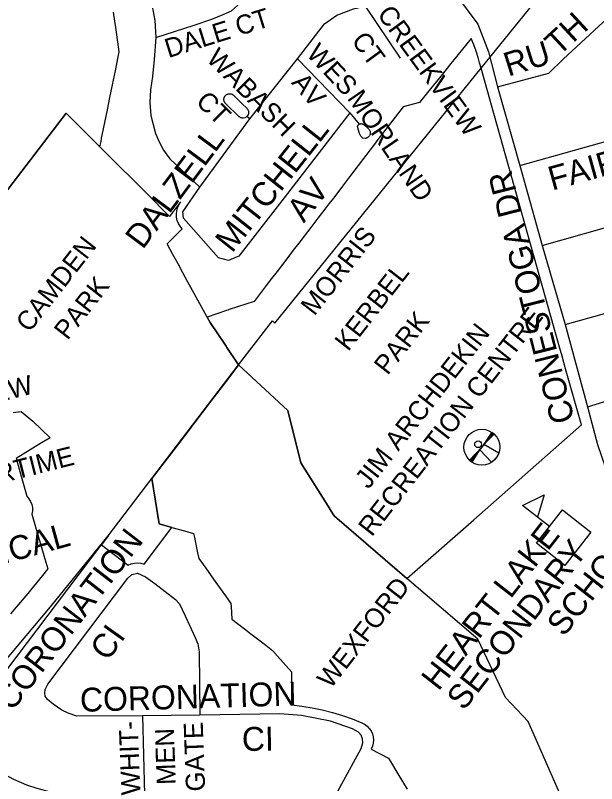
# Model space of a CAD drawing. Extents: x 586326 to 623965, y 4819854 to 4857850.
# Drawn here: x 597005 to 597614, y 4840854 to 4841658 of the extents above; entities that cross this region are included whole.
import ezdxf

# ---------------------------------------------------------------- set-up
doc = ezdxf.new("R2010")
doc.units = 0
for name, color, linetype in [('Lots_Concessions', 7, 'Continuous'), ('Minor Rd Lbls', 7, 'Continuous'), ('Minor Rds', 7, 'Continuous'), ('Park Lbls', 7, 'Continuous'), ('Park Outlines', 7, 'Continuous'), ('Proposed Secondary Rds', 7, 'Continuous'), ('Rec Lbls', 7, 'Continuous'), ('Rec Syms', 7, 'Continuous'), ('School Syms_Lbls', 7, 'Continuous'), ('Secondary Rds Lbls', 7, 'Continuous')]:
    doc.layers.add(name, color=color, linetype=linetype)

msp = doc.modelspace()

# ---------------------------------------------------------------- linework, layer by layer
at = {"layer": 'Lots_Concessions'}
for p, q in [((597492.8, 4841602.45), (597648.92, 4841795.28)), ((597492.8, 4841602.45), (597566.85, 4841693.91)), ((597276.97, 4841335.87), (597492.8, 4841602.45)), ((597239.14, 4841292.03), (597274.52, 4841338.28)), ((597274.52, 4841338.28), (597276.97, 4841335.87)), ((597148.4, 4841173.28), (597239.14, 4841292.03)), ((597102.63, 4841113.22), (597148.4, 4841173.28)), ((596954.95, 4840918.59), (597102.63, 4841113.22))]:
    msp.add_line(p, q, dxfattribs=at)
at = {"layer": 'Minor Rds'}
for points in [[(597509.86, 4841583.05), (597563.65, 4841597.08), (597578.61, 4841611.85), (597699.29, 4841723.95)], [(597134.5, 4841711.67), (597143.12, 4841688.57), (597148.22, 4841669.1), (597151.41, 4841652.39), (597152.63, 4841634.5)], [(597152.63, 4841634.5), (597192.62, 4841647.32), (597211.05, 4841653.86), (597222.91, 4841658.48), (597231.69, 4841662.41), (597238.03, 4841668.08), (597254.63, 4841691.28)], [(597300.55, 4841612.28), (597328.91, 4841648.79), (597341.81, 4841657.98), (597359.46, 4841664.34), (597371.38, 4841667.4)], [(597371.38, 4841667.4), (597408.04, 4841612.75)], [(597152.63, 4841634.5), (597150.88, 4841611.41), (597148.93, 4841593.64), (597146.88, 4841579.82), (597146.12, 4841566.64), (597147.21, 4841553.09), (597149.54, 4841543.39), (597152.24, 4841534.18), (597155.87, 4841525.5), (597160.5, 4841516.8), (597167.2, 4841507.5), (597198.36, 4841477.83)], [(597250.84, 4841549.29), (597300.55, 4841612.28)], [(597300.55, 4841612.28), (597355.51, 4841555.57)], [(597247.86, 4841551.98), (597246.99, 4841551.25), (597245.75, 4841550.63), (597244.37, 4841550.3), (597243.19, 4841550.21), (597242.98, 4841550.23), (597242.78, 4841550.27), (597241.98, 4841550.44), (597241.78, 4841550.49), (597241.58, 4841550.55), (597241.39, 4841550.63), (597241.2, 4841550.72), (597240.49, 4841551.11), (597240.31, 4841551.21), (597240.13, 4841551.33), (597239.97, 4841551.45), (597239.82, 4841551.59), (597225.35, 4841565.53), (597225.18, 4841565.71), (597225.02, 4841565.9), (597224.88, 4841566.11), (597224.44, 4841566.81), (597224.34, 4841566.99), (597224.25, 4841567.17), (597224.18, 4841567.36), (597224.11, 4841567.55), (597223.88, 4841568.35), (597223.83, 4841568.55), (597223.79, 4841568.75), (597223.77, 4841568.95), (597223.76, 4841569.16), (597223.75, 4841569.99), (597223.75, 4841570.19), (597223.77, 4841570.39), (597223.8, 4841570.6), (597223.85, 4841570.8), (597224.06, 4841571.6), (597224.12, 4841571.79), (597224.2, 4841571.98), (597224.28, 4841572.17), (597224.38, 4841572.35), (597224.8, 4841573.06), (597224.91, 4841573.23), (597225.03, 4841573.4), (597225.16, 4841573.56), (597225.31, 4841573.7), (597225.74, 4841574.12)], [(597225.74, 4841574.12), (597226.06, 4841574.41), (597226.22, 4841574.54), (597226.39, 4841574.65), (597226.56, 4841574.76), (597227.3, 4841575.15), (597227.48, 4841575.24), (597227.67, 4841575.32), (597227.86, 4841575.38), (597228.06, 4841575.43), (597228.87, 4841575.61), (597229.07, 4841575.65), (597229.27, 4841575.67), (597229.48, 4841575.68), (597229.68, 4841575.68), (597230.51, 4841575.64), (597230.71, 4841575.62), (597230.91, 4841575.59), (597231.11, 4841575.54), (597231.31, 4841575.48), (597232.1, 4841575.22), (597232.34, 4841575.12), (597232.58, 4841575), (597232.81, 4841574.86), (597233.03, 4841574.71), (597233.23, 4841574.53), (597241.05, 4841566.94), (597242.9, 4841565.17), (597242.93, 4841565.13), (597247.64, 4841560.47), (597247.78, 4841560.32), (597248.32, 4841559.71), (597248.45, 4841559.55), (597248.57, 4841559.38), (597248.68, 4841559.2), (597248.77, 4841559.02), (597249.12, 4841558.28), (597249.21, 4841558.09), (597249.27, 4841557.9), (597249.33, 4841557.7), (597249.37, 4841557.49), (597249.5, 4841556.69), (597249.53, 4841556.48), (597249.54, 4841556.28), (597249.54, 4841556.07), (597249.53, 4841555.86), (597249.43, 4841555.05), (597249.4, 4841554.85), (597249.36, 4841554.64), (597249.3, 4841554.44), (597249.23, 4841554.25), (597248.92, 4841553.49), (597248.83, 4841553.3), (597248.73, 4841553.12), (597248.62, 4841552.95), (597248.5, 4841552.78), (597247.86, 4841551.98)], [(597355.51, 4841555.57), (597281.73, 4841460.47), (597239.41, 4841405.9), (597230.8, 4841402.16)], [(597355.51, 4841555.57), (597365.21, 4841543.79)], [(597198.36, 4841477.83), (597250.84, 4841549.29)], [(597250.84, 4841549.29), (597247.86, 4841551.98)], [(597365.21, 4841543.79), (597365.28, 4841543.83), (597365.49, 4841543.94), (597365.72, 4841544.04), (597365.95, 4841544.12), (597366.48, 4841544.27), (597366.71, 4841544.33), (597366.96, 4841544.37), (597367.2, 4841544.39), (597367.45, 4841544.39), (597367.7, 4841544.37), (597368.24, 4841544.3), (597368.48, 4841544.25), (597368.72, 4841544.19), (597368.95, 4841544.11), (597369.18, 4841544.01), (597369.39, 4841543.89), (597369.86, 4841543.62), (597370.03, 4841543.51), (597370.19, 4841543.39), (597370.34, 4841543.26), (597375, 4841539.02), (597375.18, 4841538.84), (597375.35, 4841538.64), (597375.86, 4841537.99), (597375.99, 4841537.81), (597376.1, 4841537.62), (597376.2, 4841537.43), (597376.29, 4841537.23), (597376.59, 4841536.46), (597376.66, 4841536.25), (597376.72, 4841536.04), (597376.76, 4841535.82), (597376.78, 4841535.61), (597376.85, 4841534.78), (597376.85, 4841534.56), (597376.85, 4841534.34), (597376.82, 4841534.12), (597376.79, 4841533.91), (597376.61, 4841533.1), (597376.55, 4841532.88), (597376.48, 4841532.68), (597376.4, 4841532.47), (597376.3, 4841532.28), (597375.9, 4841531.55), (597375.65, 4841531.18), (597375.34, 4841530.84), (597374.77, 4841530.3)], [(597533.24, 4841500.61), (597702.65, 4841548.1)], [(597374.77, 4841530.3), (597374.13, 4841529.83), (597373.43, 4841529.44), (597373.19, 4841529.33), (597372.95, 4841529.23), (597372.7, 4841529.16), (597371.92, 4841528.97), (597371.67, 4841528.92), (597371.41, 4841528.89), (597368.94, 4841529.38), (597367.05, 4841531.24), (597365.48, 4841534.01), (597364.54, 4841537.53), (597363.57, 4841541.41), (597364.36, 4841543.04), (597365.21, 4841543.79)], [(597556.63, 4841417), (597822.65, 4841492.42), (597849.55, 4841508.21), (597890.17, 4841542.42)], [(597230.8, 4841402.16), (597228.63, 4841401.22), (597218.11, 4841404.14), (597181.28, 4841445.65), (597180.69, 4841452.08), (597198.36, 4841477.83)], [(597580.71, 4841334.36), (597958.13, 4841439.54), (597965.77, 4841440.98), (597971.84, 4841441.45), (597980.27, 4841440.98), (597988.01, 4841439.74), (597996.75, 4841436.74), (598003.13, 4841433.54), (598007.86, 4841430.42), (598014.54, 4841424.79), (598038.29, 4841400.86), (598039.72, 4841398.11), (598040.09, 4841395.77), (598040.07, 4841392.52)], [(597604.23, 4841248.33), (597689.35, 4841274.34)], [(597138.46, 4840925.09), (597069.97, 4840924.78), (597060.68, 4840927.61), (597054.14, 4840930.9), (597045, 4840937.18), (597039.2, 4840941.94), (597036.8, 4840945.63), (597036.32, 4840949), (597036.73, 4840952.54), (597039.36, 4840958.11), (597123.3, 4841068.88), (597127.5, 4841072.92), (597133.27, 4841074.33), (597141.63, 4841070.42), (597151.44, 4841063.47), (597172.9, 4841046.68), (597177.26, 4841042.03), (597183, 4841029.56), (597193.67, 4841007.08), (597196.27, 4841000.22), (597197.77, 4840991.82), (597198.53, 4840925.55)], [(597198.53, 4840925.55), (597138.46, 4840925.09)], [(597334.97, 4840831.49), (597367.47, 4840890.88), (597368.97, 4840896.85), (597368.83, 4840901.03), (597367.28, 4840904.75), (597364.39, 4840908.04), (597358.16, 4840911.31), (597335.13, 4840919.32), (597304.91, 4840925.31), (597282.35, 4840926.95), (597198.53, 4840925.55)], [(597138.46, 4840925.09), (597140.79, 4840842.66)]]:
    msp.add_lwpolyline(points, dxfattribs=at)
at = {"layer": 'Park Outlines'}
for points in [[(596979.02, 4841451.97), (597058.5, 4841555.49), (597069.52, 4841544.53), (597080.53, 4841533.57), (597084.42, 4841529.7), (597086.98, 4841527.16), (597093.95, 4841520.22), (597095.11, 4841525.9), (597095.78, 4841529.17), (597096.45, 4841532.45), (597099.12, 4841545.57), (597101.79, 4841558.69), (597104.47, 4841571.8), (597107.14, 4841584.92), (597110.15, 4841599.68), (597113.16, 4841614.43), (597114.2, 4841619.53), (597112.69, 4841629.94), (597110.5, 4841645.06), (597109.54, 4841651.7), (597108.17, 4841661.12)], [(596949.11, 4840928.35), (597042.38, 4841038.85), (597102.63, 4841113.22), (597095.54, 4841103.91), (597123.66, 4841082.57), (597126.8, 4841083.91), (597130.12, 4841084.69), (597133.53, 4841084.9), (597136.93, 4841084.52), (597140.21, 4841083.57), (597169.38, 4841122.05), (597155.83, 4841125.78), (597148.4, 4841173.28), (597175.02, 4841208.22), (597210.1, 4841254.07), (597219.45, 4841266.29), (597228.8, 4841278.51), (597239.14, 4841292.03), (597237.55, 4841294.38), (597226.87, 4841310.24), (597225.9, 4841311.67), (597209.32, 4841336.3), (597206.11, 4841342.13), (597192.52, 4841366.83), (597185.7, 4841379.35), (597180.71, 4841388.5), (597175.73, 4841397.64), (597170.25, 4841407.71), (597164.31, 4841418.62), (597179.98, 4841434.26), (597180.19, 4841434.49), (597177.99, 4841437.08), (597176.23, 4841439.99), (597174.96, 4841443.14), (597174.2, 4841446.45), (597173.98, 4841449.84), (597174.29, 4841453.23), (597175.15, 4841456.52), (597176.51, 4841459.63), (597178.35, 4841462.49), (597166.86, 4841447.45), (597163.46, 4841450.86), (597158.18, 4841456.17), (597151.67, 4841462.71), (597145.16, 4841469.24), (597142.81, 4841471.6), (597138.64, 4841475.76), (597132.1, 4841482.26), (597125.57, 4841488.76), (597116.63, 4841497.65), (597105.83, 4841508.4), (597093.95, 4841520.22), (597086.98, 4841527.16), (597084.42, 4841529.7), (597080.53, 4841533.57), (597069.52, 4841544.53), (597058.5, 4841555.49), (596979.02, 4841451.97)], [(597576.23, 4840841.2), (597542.08, 4840919.08), (597518.43, 4840944.13), (597489.29, 4841005.11), (597415.28, 4841068.65), (597339.41, 4841133.77), (597337.75, 4841136.4), (597331.04, 4841147.06), (597304.35, 4841189.47), (597290.73, 4841244.26), (597239.14, 4841292.03), (597228.8, 4841278.51), (597219.45, 4841266.29), (597210.1, 4841254.07), (597175.02, 4841208.22), (597148.4, 4841173.28), (597155.83, 4841125.78), (597169.38, 4841122.05), (597182.36, 4841118.49), (597192, 4841115.84), (597192.87, 4841111.67), (597196.23, 4841095.43), (597197.42, 4841089.69), (597204.68, 4841079.46), (597215.41, 4841064.34), (597225.34, 4841050.35), (597230.93, 4841042.47), (597231.17, 4841039.25), (597232.14, 4841026.06), (597246.73, 4841014.83), (597251.87, 4841010.87), (597265.81, 4841000.14), (597274.48, 4840993.48), (597279.79, 4840987.5), (597294.4, 4840971.06), (597294.46, 4840936.39), (597305.28, 4840935.18), (597316.03, 4840933.48), (597326.7, 4840931.3), (597337.26, 4840928.64), (597347.69, 4840925.5), (597357.97, 4840921.89), (597368.07, 4840917.83), (597370.98, 4840916.29), (597373.59, 4840914.29), (597375.84, 4840911.89), (597377.67, 4840909.16), (597379.02, 4840906.16), (597379.87, 4840902.98), (597380.18, 4840899.71), (597379.95, 4840896.42), (597379.18, 4840893.22), (597377.91, 4840890.19), (597395.87, 4840880.82), (597407.91, 4840860.73), (597415.4, 4840848.23)], [(597003.22, 4841242.37), (597011.49, 4841243.16), (597023.88, 4841233.13), (597041.81, 4841215.91), (597031.1, 4841209.39), (597013.73, 4841198.84), (597006.17, 4841194.24), (597017.52, 4841154.7), (597019.72, 4841152.13), (597021.45, 4841149.22), (597022.66, 4841146.06), (597023.31, 4841142.74), (597023.39, 4841139.36), (597022.89, 4841136.01), (597035.33, 4841092.77), (597039.37, 4841078.7), (597039.14, 4841078.42), (597033.83, 4841071.85), (597021.26, 4841056.34), (597018.46, 4841053.01), (597000.38, 4841031.6)]]:
    msp.add_lwpolyline(points, dxfattribs=at)
msp.add_lwpolyline([(597255.36, 4841358.53), (597229.27, 4841349.84), (597227.79, 4841349.35), (597226.32, 4841348.86), (597206.11, 4841342.13), (597209.32, 4841336.3), (597225.9, 4841311.67), (597226.87, 4841310.24), (597237.55, 4841294.38), (597239.14, 4841292.03), (597290.73, 4841244.26), (597304.35, 4841189.47), (597331.04, 4841147.06), (597337.75, 4841136.4), (597339.41, 4841133.77), (597415.28, 4841068.65), (597485.17, 4841130.12), (597597.81, 4841229.31), (597581.28, 4841288.05), (597577.63, 4841301.04), (597574.92, 4841310.66), (597503.7, 4841563.75), (597492.8, 4841602.46), (597491.28, 4841607.88), (597489.67, 4841613.58), (597487.61, 4841620.31), (597485.23, 4841626.94), (597482.54, 4841633.45), (597459.89, 4841605.48), (597452.28, 4841596.08), (597436.91, 4841577.1), (597428.22, 4841566.37), (597411.13, 4841562.15), (597384.91, 4841527.74), (597381.2, 4841522.87), (597355.21, 4841488.77), (597347.82, 4841479.07), (597338.56, 4841466.92), (597333.31, 4841460.03), (597329.29, 4841454.8), (597322.12, 4841445.46), (597314.69, 4841435.78), (597307.69, 4841426.67), (597302.02, 4841419.28), (597296.35, 4841411.9), (597290.67, 4841404.51), (597285, 4841397.12), (597279.32, 4841389.73), (597273.65, 4841382.34), (597267.98, 4841374.96)], close=True, dxfattribs=at)
at = {"layer": 'Proposed Secondary Rds'}
for points in [[(597466.01, 4841680.1), (597489.24, 4841648.52), (597500.74, 4841619.39), (597509.86, 4841583.05)], [(597509.86, 4841583.05), (597533.24, 4841500.61)], [(597533.24, 4841500.61), (597556.63, 4841417)], [(597556.63, 4841417), (597580.71, 4841334.36)], [(597580.71, 4841334.36), (597604.23, 4841248.33)], [(597604.23, 4841248.33), (597614.72, 4841208.96), (597622.7, 4841185.48), (597633.22, 4841165.6), (597652.57, 4841142.9), (597679.2, 4841116.07), (597912.93, 4840907.64)], [(597067.18, 4840841.17), (597055.25, 4840842.95), (597041.13, 4840845.46), (597028.32, 4840849.11), (597017.51, 4840852.33), (597003.86, 4840858.45), (596995.5, 4840863.09), (596983.85, 4840870.6)]]:
    msp.add_lwpolyline(points, dxfattribs=at)
at = {"layer": 'Rec Syms'}
for p, q in [((597505.15, 4841220.74), (597482.08, 4841191.22)), ((597482.08, 4841191.22), (597491.38, 4841203.12))]:
    msp.add_line(p, q, dxfattribs=at)
msp.add_lwpolyline([(597493.52, 4841206), (597480.79, 4841192.32), (597482.08, 4841191.22), (597483.4, 4841190.27), (597491.38, 4841203.12), (597503.65, 4841190.16), (597504.33, 4841190.6), (597505.23, 4841191.28), (597505.78, 4841191.73), (597505.86, 4841191.81), (597506.19, 4841192.09), (597507.01, 4841192.87), (597507.68, 4841193.6), (597508.38, 4841194.44), (597508.9, 4841195.16), (597509.43, 4841195.96), (597509.7, 4841196.36), (597510.03, 4841196.96), (597510.43, 4841197.69), (597510.67, 4841198.25), (597511.33, 4841199.79), (597495.58, 4841208.63), (597506.52, 4841219.58), (597505.15, 4841220.74), (597503.9, 4841221.63)], close=True, dxfattribs=at)
for centre, radius in [((597493.62, 4841205.98), 18.74), ((597489.66, 4841209.02), 3.5)]:
    msp.add_circle(centre, radius, dxfattribs=at)
at = {"layer": 'School Syms_Lbls'}
msp.add_line((597564.51, 4841122.93), (597536.1, 4841145.13), dxfattribs=at)
for points in [[(597536.1, 4841145.13), (597558.88, 4841156.16), (597551.97, 4841132.66)], [(597550.88, 4841105.48), (597578.15, 4841140.38), (597607.75, 4841117.25), (597580.49, 4841082.35)]]:
    msp.add_lwpolyline(points, close=True, dxfattribs=at)

# ---------------------------------------------------------------- texts
at = {"layer": 'Minor Rd Lbls'}
for s, height, rotation, p in [('DALE CT', 19.998, 17.39334, (597165.56, 4841612.91)), ('CREEKVIEW', 19.998, 306.0508, (597383.36, 4841658.93)), ('TH', 25.002, 42.82635, (597574.15, 4841614.3)), ('CT', 19.998, 306.31273, (597356.38, 4841631.19)), ('WABASH', 19.998, 315.00002, (597204.28, 4841611.13)), ('WES', 19.998, 313.1228, (597308.97, 4841616.58)), ('RU ', 25.002, 17.37518, (597521.24, 4841593.47)), ('AV', 19.998, 310.79205, (597293.48, 4841586.9)), ('CT', 19.998, 315.00002, (597193.23, 4841566.36)), ('MORLAND', 19.992, 304.4843, (597352.03, 4841571.01)), ('FAIRLIGHT', 25.002, 15.52413, (597567.14, 4841474.31)), ('MITCHELL', 25.002, 51.65493, (597232.32, 4841408.19)), ('DALZELL', 25.002, 53.2475, (597138.77, 4841412)), ('AV', 25.002, 51.76694, (597307.34, 4841439.91)), ('CLEARVIEW', 19.998, 14.03626, (596872.48, 4841224.1)), ('SUMMERTIME', 19.998, 14.21587, (596891.48, 4841143.1)), ('TROPICAL', 25.002, 15.42218, (596903.5, 4841058.9)), ('CORONATION', 25.002, 52.35847, (597002.1, 4840928.68)), ('CI', 25.002, 54.53955, (597102.35, 4840981.17)), ('CORONATION', 25.002, 1.73572, (597073.48, 4840929.1)), ('WHIT-', 19.998, 92.07005, (597136.39, 4840842.37)), ('GATE', 19.998, 92.07005, (597204.16, 4840846.21)), ('MEN', 19.998, 92.07005, (597173.48, 4840853.1)), ('CI', 25.002, 0.77424, (597242.66, 4840888.19))]:
    msp.add_text(s, height=height, rotation=rotation, dxfattribs=at).set_placement(p)
at = {"layer": 'Park Lbls'}
for s, p in [('MORRIS', (597318.34, 4841342.45)), ('CAMDEN', (597020.13, 4841325.08)), ('KERBEL', (597353.78, 4841305.36)), ('PARK', (597060.11, 4841317.01)), ('PARK', (597394.94, 4841280.47)), ('WEXFORD', (597335.34, 4840952.37))]:
    msp.add_text(s, height=19.992, rotation=52.00002, dxfattribs=at).set_placement(p)
at = {"layer": 'Rec Lbls'}
for s, p in [('RECREATION CENTRE', (597378.48, 4841111.51)), ('     JIM ARCHDEKIN', (597352.21, 4841132.03))]:
    msp.add_text(s, height=20, rotation=52.00002, dxfattribs=at).set_placement(p)
at = {"layer": 'School Syms_Lbls'}
for s, p in [('HEART LAKE', (597448.18, 4840950.06)), ('SCHOOL', (597579.38, 4841006.78)), ('SECONDARY', (597474.71, 4840929.47))]:
    msp.add_text(s, height=25, rotation=52.00002, dxfattribs=at).set_placement(p)
at = {"layer": 'Secondary Rds Lbls'}
msp.add_text('CONESTOGA DR', height=25.002, rotation=104.27928, dxfattribs=at).set_placement((597590.97, 4841234.3))

doc.saveas('drawing.dxf')
